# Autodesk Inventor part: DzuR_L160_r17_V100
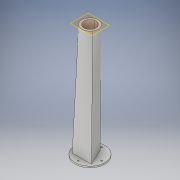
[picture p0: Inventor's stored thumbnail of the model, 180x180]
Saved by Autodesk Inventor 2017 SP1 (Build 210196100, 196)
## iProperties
Part Number: DzuR_L160_r17_V100
Material: Generisch
Document SubType Name: Modeling
Designer: haesner
Density: 1 g/cm^3
Appearance: Vorgabe
Part Number: DzuR_L160_r17_V100_3D-Druck
Author: haesner
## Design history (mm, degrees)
sketch "Skizze1"
  geometry: L1 (-1, 8.5)-(1, 8.5); L2 (1, 8.5)-(8.927, -8.5); L3 (8.927, -8.5)-(-8.927, -8.5); L4 (-8.927, -8.5)-(-1, 8.5); L5 (-19.091, 0)-(19.091, 0) reference; L6 (0, -16.1)-(0, 16.1) reference; L7 (-2.911, 11.5)-(2.911, 11.5); L8 (2.911, 11.5)-(13.636, -11.5); L9 (13.636, -11.5)-(-13.636, -11.5); L10 (-13.636, -11.5)-(-2.911, 11.5); 1 further point
  constraints: 16 end point, 4 parallel, 2 horizontal, 2 symmetric about line, 1 equal length, 2 other
  dimensions: "d0" = 2 distance of L1.start L1.end; "d1" = 17 distance between parallel lines of L3 L1; "d2" = 25 deg angle of L2 L6; "d4" = 3 distance between parallel lines of L7 L1; "d5" = 3 distance between parallel lines of L8 L2; "d6" = 3 distance between parallel lines of L9 L3 (derived)
workplane "Arbeitsebene1"
sketch "Skizze2"
  geometry: C1 r 11.5 at (0, 0); 1 further point
  constraints: 1 centre point, 1 coincident
  dimensions: "d8" = 23 diameter of C1
feature "Erhebung1" sketch "Skizze2" dims "d9" = 0, "d10" = 90 deg, "d11" = 0, "d12" = 90 deg
feature "Wandung1" dims "d13" = 3
sketch "Skizze3"
  geometry: L1 (27.273, 0)-(16.547, 23) reference; L2 (16.547, 23)-(10.725, 23) reference; L3 (10.725, 23)-(0, 0) reference; L4 (0, 0)-(27.273, 0) reference; C1 r 21 at (13.636, 11.5); 1 further point
  constraints: 1 centre point, 1 coincident
  dimensions: "d14" = 42 diameter of C1
extrude "Extrusion1" join sketch "Skizze3" distance "d15" = 2; taper "d16" = 0 deg
sketch "Skizze4"
  geometry: L1 (0, 16.5)-(-16.5, 0); L2 (-16.5, 0)-(0, -16.5); L3 (0, -16.5)-(16.5, 0); L4 (16.5, 0)-(0, 16.5); L5 (29.4, 0)-(-29.4, 0) reference; L6 (0, -29.4)-(0, 29.4) reference; 1 further point
  constraints: 8 end point, 3 point on line, 2 parallel, 2 perpendicular
  dimensions: "d17" = 16.5 distance from line of L5 L1.start
hole "Bohrung1" sketch "Skizze4" at (0, 16.5), (-16.5, 0), (16.5, 0), (0, -16.5) diameter "d18" = 2.3; stored, may be unused: countersink angle "d22" = 90 deg, drill point angle "d24" = 118 deg; dims "d19" = 6, "d20" = 4, "d21" = 2, "d23" = 8
node "Volumenkörper1"
